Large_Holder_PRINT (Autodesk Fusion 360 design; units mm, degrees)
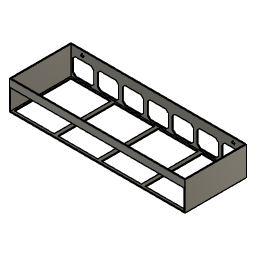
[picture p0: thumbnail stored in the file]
sketch "Bottom" plane through (0, 0, 0) normal (0, 0, 1) x axis (1, 0, 0)
  line L1 (232.6, 0) -> (0, 0)
  line L2 (232.6, 81.6) -> (232.6, 0)
  line L3 (0, 81.6) -> (232.6, 81.6)
  line L4 (0, 0) -> (0, 81.6)
  line L5 (231.4, 80.4) -> (1.2, 80.4)
  line L6 (231.4, 1.2) -> (231.4, 80.4)
  line L7 (1.2, 1.2) -> (231.4, 1.2)
  line L8 (1.2, 80.4) -> (1.2, 1.2)
  line L9 (3.2, 78.4) -> (3.2, 3.2)
  line L10 (34.2, 80.4) -> (33.4, 80.4)
  line L11 (33.4, 1.2) -> (34.2, 1.2)
  line L12 (67.2, 80.4) -> (66.4, 80.4)
  line L13 (66.4, 1.2) -> (67.2, 1.2)
  line L14 (100.2, 80.4) -> (99.4, 80.4)
  line L15 (99.4, 1.2032) -> (100.2, 1.2032)
  line L16 (133.2, 80.4) -> (132.4, 80.4)
  line L17 (132.4, 1.2) -> (133.2, 1.2)
  line L18 (166.2, 80.4) -> (165.4, 80.4)
  line L19 (165.4, 1.2) -> (166.2, 1.2)
  line L20 (199.2, 80.4) -> (198.4, 80.4)
  line L21 (198.4, 1.2) -> (199.2, 1.2)
  line L22 (229.4, 3.2) -> (229.4, 78.4)
  line L23 (232.2, 80.4) -> (231.4, 80.4)
  line L24 (231.4, 1.2) -> (232.2, 1.2)
  line L25 (113.9, 78.4) -> (3.2, 78.4)
  line L26 (3.2, 3.2) -> (113.9, 3.2)
  line L27 (118.7, 78.4) -> (229.4, 78.4)
  line L28 (113.8, 3.2) -> (229.4, 3.2)
  line L29 (113.9, 78.4) -> (118.7, 78.4)
  line L30 (113.8, 3.2) -> (113.9, 3.2)
  line L31 (56, 1.2) -> (56, 80.4)
  line L32 (61, 1.2) -> (61, 80.4)
  line L33 (113.8, 1.2) -> (113.8, 80.4)
  line L34 (118.8, 80.4) -> (118.8, 1.2)
  line L35 (171.6, 80.4) -> (171.6, 3.2)
  line L36 (176.6, 1.2) -> (176.6, 80.4)
  line L37 (171.6, 1.2) -> (171.6, 3.2)
  point P1 (0, 0)
  point P2 (0, 0)
  point P14 (34.2, 1.2)
  point P12 (33.4, 80.4)
  point P16 (66.4, 80.4)
  point P20 (99.4, 80.4)
  point P24 (132.4, 80.4)
  point P28 (165.4, 80.4)
  point P32 (198.4, 80.4)
  point P38 (231.4, 80.4)
  point P46 (56, 80.4)
  point P47 (56, 1.2)
  point P48 (61, 80.4)
  point P49 (61, 1.2)
  point P50 (113.8, 80.4)
  point P51 (113.8, 1.2)
  point P52 (118.8, 1.2)
  point P53 (118.8, 80.4)
  point P54 (171.6, 3.2)
  point P55 (171.6, 80.4)
  point P56 (176.6, 80.4)
  point P57 (176.6, 1.2)
  point P58 (171.6, 1.2)
  point P5 (0, 81.6)
  horizontal L1
  vertical L2
  horizontal L3
  vertical L4
  coincident P1 P2
  horizontal L5
  vertical L6
  horizontal L7
  vertical L8
  vertical L9
  horizontal L10
  coincident L7 P14
  coincident L5 P12
  horizontal L12
  horizontal L13
  coincident L5 P16
  horizontal L14
  horizontal L15
  coincident L5 P20
  horizontal L16
  horizontal L17
  coincident L5 P24
  horizontal L18
  horizontal L19
  coincident L5 P28
  horizontal L20
  horizontal L21
  coincident L5 P32
  vertical L22
  horizontal L23
  horizontal L24
  coincident L5 P38
  perpendicular L9 L26
  coincident L5 P46
  coincident L7 P47
  perpendicular L7 L31
  coincident L5 P48
  coincident L7 P49
  perpendicular L1 L32
  coincident L5 P50
  coincident L7 P51
  perpendicular L7 L33
  coincident L7 P52
  perpendicular L5 L34
  coincident L5 P53
  midpoint L28 P54
  coincident L5 P55
  perpendicular L5 L35
  coincident L5 P56
  coincident L7 P57
  perpendicular L7 L36
  coincident L7 P58
  perpendicular L7 L37
  dimension "d1" distance L4 L8 = 1.2
  dimension "d2" distance L3 L5 = 1.2
  dimension "d3" distance L1 L7 = 1.2
  dimension "d4" distance L2 L6 = 1.2
  dimension "d5" distance L8 L9 = 2
  dimension "d8" distance P2 P5 = 81.6
  dimension "d52" distance L6 L22 = 2
  dimension "d191" distance L5 L25 = 2
  dimension "d192" distance L7 L26 = 2
  dimension "d194" distance L7 L28 = 2
  dimension "d195" distance L5 L27 = 2
  dimension "d306" distance L31 L32 = 5
  dimension "d307" distance L33 L34 = 5
  dimension "d308" distance L9 L31 = 52.8
  dimension "d311" distance L32 L33 = 52.8
  dimension "d312" distance L34 L35 = 52.8
  dimension "d313" distance L35 L36 = 5
  dimension "d318" distance L22 L36 = 52.8
extrude "Extrude2" new body sketch "Bottom" profile of L1 L2 L3 L4 L5 L6 L7 L8 L10 L11 L12 L13 L14 L16 L17 L18 L19 L20 L21 along normal blind 38.2
sketch "Front" plane through (0, 0, 0) normal (0, -1, 0) x axis (1, 0, 0)
  line L1 (232.6, 0) -> (0, 0)
  line L2 (232.6, 38.2) -> (232.6, 0)
  line L3 (0, 38.2) -> (232.6, 38.2)
  line L4 (0, 0) -> (0, 38.2)
  line L5 (33.4, 28.2) -> (1.2, 28.2)
  line L6 (1.2, 1.2) -> (33.4, 1.2)
  line L7 (1.2, 28.2) -> (1.2, 1.2)
  line L8 (1.2, 38.2) -> (1.2, 0)
  line L9 (231.4, 1.2) -> (231.4, 28.2)
  line L10 (231.4, 28.2) -> (33.4, 28.2)
  line L11 (33.4, 1.2) -> (231.4, 1.2)
  point P6 (1.2, 28.2)
  point P9 (1.2, 1.2)
  point P12 (231.4, 28.2)
  point P13 (231.4, 1.2)
  horizontal L5
  horizontal L6
  vertical L7
  collinear L7 L8
  vertical L9
  perpendicular L9 L10
  dimension "d80" distance P6 P9 = 27
  dimension "d83" distance L3 L5 = 10
  dimension "d91" distance P12 P13 = 27
  dimension "d319" distance L2 L9 = 1.2
sketch "Back" plane through (0, 80.4, 0) normal (0, -1, 0) x axis (1, 0, 0)
  line L1 (231.4, 38.2) -> (231.4, 0)
  line L2 (1.2, 38.2) -> (231.4, 38.2)
  line L3 (1.2, 0) -> (1.2, 38.2)
  line L4 (6.7355, 3.2) -> (3.2, 6.7355)
  line L5 (27.8645, 3.2) -> (6.7355, 3.2)
  line L6 (3.2, 22.7355) -> (6.7355, 26.2711)
  line L7 (3.2, 6.7355) -> (3.2, 22.7355)
  line L8 (27.8645, 26.2711) -> (27.8645, 26.271)
  line L9 (31.4, 22.7355) -> (31.4, 6.7355)
  line L10 (27.8645, 26.2711) -> (31.4, 22.7355)
  line L11 (231.4, 0) -> (1.2, 0)
  line L12 (31.4, 6.7355) -> (27.8645, 3.2)
  line L13 (6.7355, 26.2711) -> (27.8645, 26.271)
  line L14 (39.7355, 26.2729) -> (60.8645, 26.2728)
  line L15 (36.2, 22.7374) -> (39.7355, 26.2729)
  line L16 (36.2, 6.7374) -> (36.2, 22.7374)
  line L17 (39.7355, 3.2019) -> (36.2, 6.7374)
  line L18 (60.8645, 3.2019) -> (39.7355, 3.2019)
  line L19 (64.4, 6.7374) -> (60.8645, 3.2019)
  line L20 (64.4, 22.7374) -> (64.4, 6.7374)
  line L21 (72.7355, 26.2711) -> (93.8645, 26.271)
  line L22 (69.2, 22.7355) -> (72.7355, 26.2711)
  line L23 (69.2, 6.7355) -> (69.2, 22.7355)
  line L24 (72.7355, 3.2) -> (69.2, 6.7355)
  line L25 (93.8645, 3.2) -> (72.7355, 3.2)
  line L26 (97.4, 6.7355) -> (93.8645, 3.2)
  line L27 (97.4, 22.7355) -> (97.4, 6.7355)
  line L28 (105.7355, 26.2711) -> (126.8645, 26.271)
  line L29 (102.2, 22.7355) -> (105.7355, 26.2711)
  line L30 (102.2, 6.7355) -> (102.2, 22.7355)
  line L31 (105.7355, 3.2) -> (102.2, 6.7355)
  line L32 (126.8645, 3.2) -> (105.7355, 3.2)
  line L33 (130.4, 6.7355) -> (126.8645, 3.2)
  line L34 (130.4, 22.7355) -> (130.4, 6.7355)
  line L35 (138.7355, 26.2711) -> (159.8645, 26.271)
  line L36 (135.2, 22.7355) -> (138.7355, 26.2711)
  line L37 (135.2, 6.7355) -> (135.2, 22.7355)
  line L38 (138.7355, 3.2) -> (135.2, 6.7355)
  line L39 (159.8645, 3.2) -> (138.7355, 3.2)
  line L40 (163.4, 6.7355) -> (159.8645, 3.2)
  line L41 (163.4, 22.7355) -> (163.4, 6.7355)
  line L42 (171.7355, 26.2711) -> (192.8645, 26.271)
  line L43 (168.2, 22.7355) -> (171.7355, 26.2711)
  line L44 (168.2, 6.7355) -> (168.2, 22.7355)
  line L45 (171.7355, 3.2) -> (168.2, 6.7355)
  line L46 (192.8645, 3.2) -> (171.7355, 3.2)
  line L47 (196.4, 6.7355) -> (192.8645, 3.2)
  line L48 (196.4, 22.7355) -> (196.4, 6.7355)
  line L49 (204.7355, 26.2711) -> (225.8645, 26.271)
  line L50 (201.2, 22.7355) -> (204.7355, 26.2711)
  line L51 (201.2, 6.7355) -> (201.2, 22.7355)
  line L52 (204.7355, 3.2) -> (201.2, 6.7355)
  line L53 (225.8645, 3.2) -> (204.7355, 3.2)
  line L54 (229.4, 6.7355) -> (225.8645, 3.2)
  line L55 (229.4, 22.7355) -> (229.4, 6.7355)
  line L56 (232.6, 38.2) -> (232.6, 0)
  line L57 (0, 38.2) -> (0, 0)
  line L58 (64.4, 22.7374) -> (60.8645, 26.2728)
  line L59 (93.8645, 26.271) -> (97.4, 22.7355)
  line L60 (126.8645, 26.271) -> (130.4, 22.7355)
  line L61 (159.8645, 26.271) -> (163.4, 22.7355)
  line L62 (192.8645, 26.271) -> (196.4, 22.7355)
  line L63 (225.8645, 26.271) -> (229.4, 22.7355)
  point P9 (6.7355, 26.2711)
  point P10 (3.2, 22.7355)
  point P5 (3.2, 6.7355)
  point P6 (6.7355, 3.2)
  point P12 (31.4, 22.7355)
  point P13 (27.8645, 26.2711)
  point P7 (27.8645, 3.2)
  point P11 (31.4, 6.7355)
  point P8 (27.8645, 26.271)
  point P22 (36.2, 22.7374)
  point P24 (39.7355, 26.2729)
  point P19 (36.2, 6.7374)
  point P23 (39.7355, 3.2019)
  point P17 (64.4, 6.7374)
  point P20 (60.8645, 3.2019)
  point P18 (64.4, 22.7374)
  point P21 (60.8645, 26.2728)
  point P30 (69.2, 22.7355)
  point P32 (72.7355, 26.2711)
  point P27 (69.2, 6.7355)
  point P31 (72.7355, 3.2)
  point P25 (97.4, 6.7355)
  point P28 (93.8645, 3.2)
  point P29 (93.8645, 26.271)
  point P38 (102.2, 22.7355)
  point P40 (105.7355, 26.2711)
  point P35 (102.2, 6.7355)
  point P39 (105.7355, 3.2)
  point P33 (130.4, 6.7355)
  point P36 (126.8645, 3.2)
  point P34 (130.4, 22.7355)
  point P37 (126.8645, 26.271)
  point P46 (135.2, 22.7355)
  point P48 (138.7355, 26.2711)
  point P43 (135.2, 6.7355)
  point P47 (138.7355, 3.2)
  point P41 (163.4, 6.7355)
  point P44 (159.8645, 3.2)
  point P42 (163.4, 22.7355)
  point P45 (159.8645, 26.271)
  point P54 (168.2, 22.7355)
  point P56 (171.7355, 26.2711)
  point P51 (168.2, 6.7355)
  point P55 (171.7355, 3.2)
  point P49 (196.4, 6.7355)
  point P52 (192.8645, 3.2)
  point P50 (196.4, 22.7355)
  point P53 (192.8645, 26.271)
  point P62 (201.2, 22.7355)
  point P64 (204.7355, 26.2711)
  point P59 (201.2, 6.7355)
  point P63 (204.7355, 3.2)
  point P57 (229.4, 6.7355)
  point P60 (225.8645, 3.2)
  point P58 (229.4, 22.7355)
  point P61 (225.8645, 26.271)
  parallel L3 L7
  vertical L9
  vertical L20
  vertical L27
  vertical L34
  vertical L41
  vertical L48
  vertical L55
  dimension "d97" distance P9 P10 = 5
  dimension "d99" distance P5 P6 = 5
  dimension "d179" distance P12 P13 = 5
  dimension "d201" distance L7 L9 = 28.2
  dimension "d202" distance P7 P11 = 5
  dimension "d206" distance L5 L11 = 3.2
  dimension "d208" angle L4 L5 = 135
  dimension "d209" angle L9 L12 = 135
  dimension "d210" angle L9 L10 = 135
  dimension "d212" distance P5 P10 = 16
  dimension "d213" distance P8 P9 = 21.1289
  dimension "d215" angle L6 L13 = 135
  dimension "d216" angle L10 L13 = 135
  dimension "d219" distance P22 P24 = 5
  dimension "d220" distance P19 P23 = 5
  dimension "d222" distance L16 L20 = 28.2
  dimension "d223" distance P17 P20 = 5
  dimension "d224" distance P17 P18 = 16
  dimension "d225" angle L17 L18 = 135
  dimension "d226" angle L19 L20 = 135
  dimension "d228" distance P19 P22 = 16
  dimension "d229" distance P21 P24 = 21.1289
  dimension "d230" angle L14 L15 = 135
  dimension "d232" distance P30 P32 = 5
  dimension "d233" distance P27 P31 = 5
  dimension "d235" distance L23 L27 = 28.2
  dimension "d236" distance P25 P28 = 5
  dimension "d238" angle L24 L25 = 135
  dimension "d239" angle L26 L27 = 135
  dimension "d241" distance P27 P30 = 16
  dimension "d242" distance P29 P32 = 21.1289
  dimension "d243" angle L21 L22 = 135
  dimension "d245" distance P38 P40 = 5
  dimension "d246" distance P35 P39 = 5
  dimension "d248" distance L30 L34 = 28.2
  dimension "d249" distance P33 P36 = 5
  dimension "d250" distance P33 P34 = 16
  dimension "d251" angle L31 L32 = 135
  dimension "d252" angle L33 L34 = 135
  dimension "d254" distance P35 P38 = 16
  dimension "d255" distance P37 P40 = 21.1289
  dimension "d256" angle L28 L29 = 135
  dimension "d258" distance P46 P48 = 5
  dimension "d259" distance P43 P47 = 5
  dimension "d261" distance L37 L41 = 28.2
  dimension "d262" distance P41 P44 = 5
  dimension "d263" distance P41 P42 = 16
  dimension "d264" angle L38 L39 = 135
  dimension "d265" angle L40 L41 = 135
  dimension "d267" distance P43 P46 = 16
  dimension "d268" distance P45 P48 = 21.1289
  dimension "d269" angle L35 L36 = 135
  dimension "d271" distance P54 P56 = 5
  dimension "d272" distance P51 P55 = 5
  dimension "d274" distance L44 L48 = 28.2
  dimension "d275" distance P49 P52 = 5
  dimension "d276" distance P49 P50 = 16
  dimension "d277" angle L45 L46 = 135
  dimension "d278" angle L47 L48 = 135
  dimension "d280" distance P51 P54 = 16
  dimension "d281" distance P53 P56 = 21.1289
  dimension "d282" angle L42 L43 = 135
  dimension "d284" distance P62 P64 = 5
  dimension "d285" distance P59 P63 = 5
  dimension "d287" distance L51 L55 = 28.2
  dimension "d288" distance P57 P60 = 5
  dimension "d289" distance P57 P58 = 16
  dimension "d290" angle L52 L53 = 135
  dimension "d291" angle L54 L55 = 135
  dimension "d293" distance P59 P62 = 16
  dimension "d294" distance P61 P64 = 21.1289
  dimension "d295" angle L49 L50 = 135
  dimension "d297" distance L9 L16 = 4.8
  dimension "d298" distance L20 L23 = 4.8
  dimension "d299" distance L27 L30 = 4.8
  dimension "d300" distance L34 L37 = 4.8
  dimension "d301" distance L41 L44 = 4.8
  dimension "d302" distance L48 L51 = 4.8
  dimension "d304" distance L7 L57 = 3.2
  dimension "d305" distance P42 P45 = 4.9999
  dimension "d320" distance L11 L18 = 3.2019
  dimension "d321" distance L11 L25 = 3.2
  dimension "d323" distance L11 L32 = 3.2
  dimension "d297" distance = 3.4645
  dimension "d298" distance = 3.4645
sketch "Mounting" plane through (0, 80.4, 0) normal (0, -1, 0) x axis (1, 0, 0)
  line L1 (231.4, 38.2) -> (231.4, 0)
  line L2 (1.2, 38.2) -> (231.4, 38.2)
  line L3 (1.2, 0) -> (1.2, 38.2)
  line L4 (231.4, 0) -> (1.2, 0)
  circle C1 centre (216.3, 32.2) radius 2
  circle C2 centre (16.3, 32.2) radius 2
  point P6 (16.3, 32.2)
  point P5 (216.3, 32.2)
  dimension "d165" diameter C1 = 4
  dimension "d166" diameter C2 = 4
  dimension "d167" distance L3 P6 = 15.1
  dimension "d168" distance L2 P6 = 6
  dimension "d169" distance L1 P5 = 15.1
  dimension "d170" distance L2 P5 = 6
extrude "Extrude9" cut sketch "Front" profile of L5 L6 L7 L8 L9 L10 L11 to an object
extrude "Extrude10" cut sketch "Back" profile of L4 L5 L6 L7 L8 L9 L10 L12 L13 L14 L15 L16 L17 L18 L19 L20 L21 L22 L23 L24 L25 L26 L27 L28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 against normal blind 1.2
extrude "Extrude11" cut sketch "Mounting" profile of C1 C2 against normal blind 1.2
extrude "Extrude12" add sketch "Bottom" profile of L5 L7 L8 L9 L10 L11 L12 L13 L14 to an object
extrude "Extrude13" add sketch "Bottom" profile of L5 L6 L7 L16 L17 L18 L19 L20 L21 L22 L27 L28 to an object
extrude "Extrude15" add sketch "Bottom" profile of L25 L26 L27 L28 L29 L30 L31 L32 L33 L34 L35 L36 along normal blind 1.2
